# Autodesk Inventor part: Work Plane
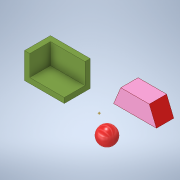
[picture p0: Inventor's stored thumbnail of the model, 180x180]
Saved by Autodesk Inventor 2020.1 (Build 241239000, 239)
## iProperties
Created: 2018-06
Part Number: Work Plane
Material: Generic
Document SubType Name: Modeling
Designer: Power User
Density: 1 g/cm^3
Appearance: Light Red
Author: Power User
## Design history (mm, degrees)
sketch "Sketch1"
  geometry: L1 (0, 0)-(50, 0); L2 (50, 0)-(50, -50); L3 (50, -50)-(0, -50); L4 (0, -50)-(0, 0); 1 further point
  constraints: 8 end point, 2 parallel, 1 coincident, 1 horizontal, 1 perpendicular
  dimensions: "d0" = 50 distance of L1.end L2.end; "d1" = 50 distance of L2.end L3.end; "d53" = 0 distance from line of point (0, 0) L4
extrude "Extrusion1" new body sketch "Sketch1" distance "d2" = 50; taper "d3" = 0 deg
workplane "Work Plane1"
sketch "Sketch2"
  geometry: L1 (0, 50)-(50, 50) reference; L2 (50, 0)-(50, 50) reference; C1 r 20 at (-30, 25); 3 further points
  constraints: 2 midpoint, 1 centre point, 1 horizontal alignment
  dimensions: "d5" = 40 diameter of C1; "d54" = 30 horizontal distance of C1.centre point (0, 0)
extrude "Extrusion2" new body sketch "Sketch2" distance "d6" = 50; taper "d7" = 0 deg
sketch "Sketch3"
  geometry: L1 (-172.16, 49.98)-(-172.16, 11.482); C1 r 7.5 at (-197.16, 26.587); 1 further point
  constraints: 2 end point, 1 centre point, 1 vertical
  dimensions: "d8" = 15 diameter of C1; "d9" = 50 diameter of C1.centre L1
revolve "Revolution1" sketch "Sketch3" stored, may be unused: angle "d10" = 90 deg
workplane "Work Plane2"
sketch "Sketch4"
  geometry: L1 (-98.807, 58.325)-(-98.807, 8.325); A1 r 25 centre (-98.807, 33.325) between (-98.807, 58.325) and (-98.807, 8.325); 1 further point
  constraints: 2 end point, 2 point on circle, 1 centre point, 1 vertical
  dimensions: "d12" = 50 diameter of A1
revolve "Revolution2" sketch "Sketch4" stored, may be unused: angle "d13" = 90 deg
workplane "Work Plane3"
sketch "Sketch5"
  geometry: L1 (-192.037, 9.98)-(-171.326, 59.98); L2 (-171.326, 59.98)-(-89.041, 59.98); L3 (-89.041, 59.98)-(-68.33, 9.98); L4 (-68.33, 9.98)-(-192.037, 9.98); L5 (-130.184, 59.98)-(-130.184, 9.98); 1 further point
  constraints: 10 end point, 2 midpoint, 1 horizontal, 1 parallel, 1 perpendicular, 1 other
  dimensions: "d15" = 50 distance between parallel lines of L4 L2; "d16" = 45 deg angle of L3 L1
extrude "Extrusion3" new body sketch "Sketch5" stored distance "d17" = 50; taper "d18" = 0 deg
sketch "Sketch6"
  geometry: L1 (15, 35)-(35, 35); L2 (35, 35)-(35, 15); L3 (35, 15)-(15, 15); L4 (15, 15)-(15, 35); L5 (0, 50)-(50, 50) reference; L6 (0, 0)-(0, 50) reference; 5 further points
  constraints: 4 midpoint, 1 horizontal alignment, 1 vertical alignment, 2 other
  dimensions: "d19" = 20 distance of L1.start L1.end; "d20" = 20 distance of L1.end L2.end
emboss "Emboss1" sketch "Sketch6" dims "d0" = 50, "d1" = 50, "d12" = 50, "d21" = 0.2, "d22" = 0, "d53" = 0
sketch "Sketch7"
  geometry: L1 (-35, 35)-(-15, 35); L2 (-15, 35)-(-15, 15); L3 (-15, 15)-(-35, 15); L4 (-35, 15)-(-35, 35); L5 (0, 50)-(-50, 50) reference; L6 (-50, 50)-(-50, 0) reference; 5 further points
  constraints: 4 midpoint, 1 horizontal alignment, 1 vertical alignment, 2 other
  dimensions: "d23" = 20 distance of L1.start L1.end; "d24" = 20 distance of L3.end L1.start
emboss "Emboss2" sketch "Sketch7" dims "d0" = 50, "d1" = 50, "d12" = 50, "d25" = 0.2, "d26" = 0, "d53" = 0
sketch "Sketch8"
  geometry: L1 (15, 35)-(35, 35); L2 (35, 35)-(35, 15); L3 (35, 15)-(15, 15); L4 (15, 15)-(15, 35); L5 (0, 0)-(0, 50) reference; L6 (0, 50)-(50, 50) reference; 4 further points
  constraints: 4 midpoint, 1 horizontal alignment, 1 vertical alignment, 2 other
  dimensions: "d27" = 20 distance of L1.start L1.end; "d28" = 20 distance of L3.end L1.start
emboss "Emboss3" sketch "Sketch8" dims "d0" = 50, "d1" = 50, "d12" = 50, "d29" = 0.2, "d30" = 0, "d53" = 0
sketch "Sketch9"
  geometry: L1 (-11.219, -35.018)-(-35.694, -35.018); L2 (-35.694, -35.018)-(-35.694, -14.982); L3 (-35.694, -14.982)-(-11.219, -14.982); L4 (-11.219, -14.982)-(-11.219, -35.018); L5 (0, -50)-(0, 0) reference; 4 further points
  constraints: 3 midpoint, 1 horizontal alignment, 1 vertical alignment, 2 other
emboss "Emboss4" sketch "Sketch9" dims "d0" = 50, "d1" = 50, "d12" = 50, "d31" = 0.2, "d32" = 0, "d53" = 0
sketch "Sketch10"
  geometry: L1 (15, 35)-(35, 35); L2 (35, 35)-(35, 15); L3 (35, 15)-(15, 15); L4 (15, 15)-(15, 35); L5 (0, 50)-(50, 50) reference; L6 (0, 0)-(0, 50) reference; 5 further points
  constraints: 4 midpoint, 1 horizontal alignment, 1 vertical alignment, 2 other
  dimensions: "d33" = 20 distance of L1.start L1.end; "d34" = 20 distance of L3.end L1.start
emboss "Emboss5" sketch "Sketch10" dims "d0" = 50, "d1" = 50, "d12" = 50, "d35" = 0.2, "d36" = 0, "d53" = 0
sketch "Sketch11"
  geometry: L1 (15, 35)-(35, 35); L2 (35, 35)-(35, 15); L3 (35, 15)-(15, 15); L4 (15, 15)-(15, 35); L5 (0, 0)-(0, 50) reference; L6 (0, 50)-(50, 50) reference; 4 further points
  constraints: 4 midpoint, 1 horizontal alignment, 1 vertical alignment, 2 other
  dimensions: "d37" = 20 distance of L1.start L1.end; "d38" = 20 distance of L1.end L2.end
emboss "Emboss6" sketch "Sketch11" dims "d0" = 50, "d1" = 50, "d12" = 50, "d39" = 0.2, "d40" = 0, "d53" = 0
sketch "Sketch12"
  geometry: L1 (118.439, 97.246)-(43.439, 97.246); L2 (43.439, 97.246)-(43.439, 172.246); L3 (43.439, 172.246)-(58.439, 172.246); L4 (58.439, 172.246)-(58.439, 112.246); L5 (58.439, 112.246)-(118.439, 112.246); L6 (118.439, 112.246)-(118.439, 97.246); 1 further point
  constraints: 12 end point, 4 perpendicular, 1 horizontal, 1 vertical
  dimensions: "d41" = 75 distance of L1.start L1.end; "d42" = 75 distance of L1.end L2.end (= d41); "d43" = 15 distance of L5.end L1.start; "d44" = 15 distance of L2.end L3.end (= d43)
extrude "Extrusion4" new body sketch "Sketch12" stored distance "d45" = 100; taper "d46" = 0 deg
sketch "Sketch13"
  geometry: L1 (97.246, 118.439)-(97.246, 43.439) reference; L2 (97.246, 43.439)-(172.246, 43.439) reference; L3 (172.246, 43.439)-(97.246, 43.439) reference; L4 (172.246, 118.439)-(97.246, 118.439); L5 (97.246, 118.439)-(97.246, 43.439); L6 (97.246, 43.439)-(172.246, 43.439); L7 (172.246, 43.439)-(172.246, 118.439); L8 (172.246, 118.439)-(97.246, 43.439); L9 (97.246, 118.439)-(172.246, 43.439); 2 further points
  constraints: 12 end point, 2 equal length, 2 midpoint, 2 parallel, 1 horizontal, 1 perpendicular
extrude "Extrusion5" join sketch "Sketch13" distance "d47" = 15; taper "d48" = 0 deg
feature "Move Body1"
workpoint "Work Point3"
node "Cube"
node "Cylinder"
node "Ring"
node "Sphere"
node "Trapezoid"
node "Solid"
other parameters: "d14" = -87.5
